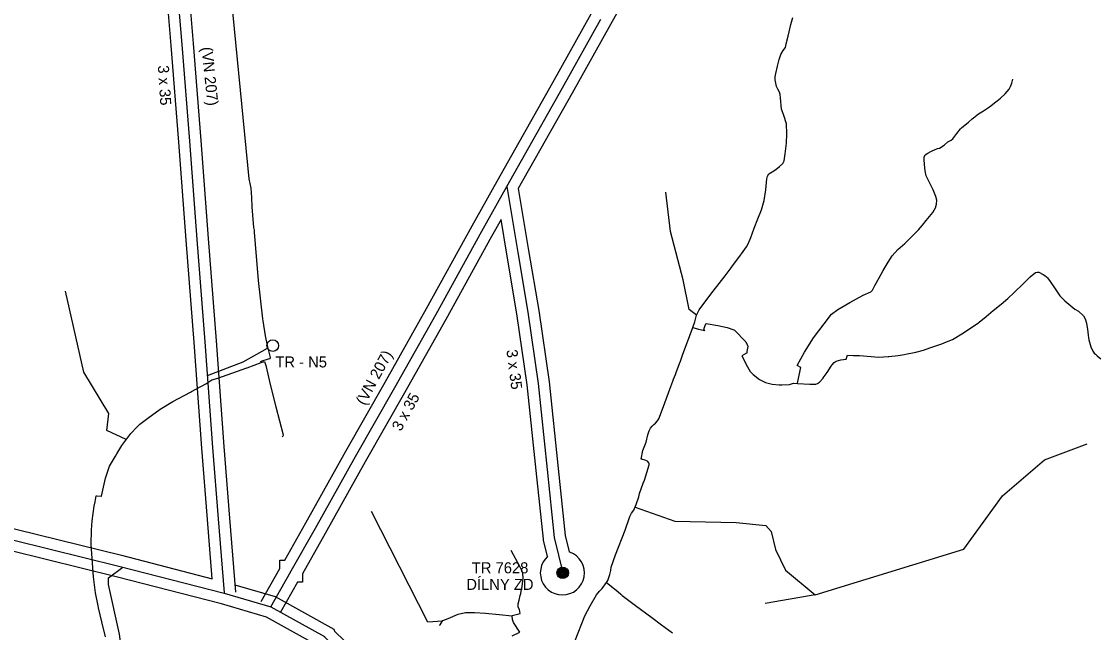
# Model space of a CAD drawing. Extents: x -439095 to -431527, y -1129525 to -1119219.
# Drawn here: x -438161 to -437185, y -1123936 to -1123382 of the extents above; entities that cross this region are included whole.
import ezdxf

# ---------------------------------------------------------------- set-up
doc = ezdxf.new("R2010")
doc.units = 0
for name, color, linetype in [('Hranice reseneho uzemi', 7, 'Continuous'), ('UZEMNI REZERVA', 7, 'Continuous'), ('Vrstva 11', 7, 'Continuous'), ('Vrstva 13', 7, 'Continuous'), ('Vrstva 19', 7, 'Continuous'), ('Vrstva 21', 7, 'Continuous'), ('ZU', 7, 'Continuous')]:
    doc.layers.add(name, color=color, linetype=linetype)

msp = doc.modelspace()

# ---------------------------------------------------------------- linework, layer by layer
at = {"layer": 'Hranice reseneho uzemi'}
for points in [[(-437977.03, -1123900.4), (-437982.65, -1123833.3), (-437982.65, -1123833.3), (-437987.74, -1123768.43), (-437994.75, -1123672.68), (-438001.8, -1123579.96), (-438008.51, -1123491), (-438015.39, -1123403.36), (-438022.11, -1123324.98), (-438003.06, -1123258.21), (-438003.06, -1123258.21), (-437981.89, -1123195.97)], [(-437935.03, -1123912.96), (-437916.84, -1123880.87), (-437916.84, -1123880.59), (-437916.74, -1123880.59), (-437916.62, -1123880.59), (-437916.52, -1123880.59), (-437916.52, -1123880.31), (-437894.53, -1123841.62), (-437858.3, -1123776.7), (-437822.65, -1123714.13), (-437785.14, -1123647.58), (-437743.7, -1123572.45), (-437721.24, -1123531.98), (-437670.6, -1123442.65), (-437636.02, -1123380.39)], [(-437721.24, -1123531.98), (-437711.29, -1123591.69), (-437702.05, -1123645.92), (-437692.72, -1123710.41), (-437684.69, -1123788.49), (-437678.09, -1123850.04), (-437678.09, -1123850.04), (-437670.47, -1123882.16), (-437670.23, -1123882.16), (-437670.23, -1123882.27)], [(-437992.51, -1123703.22), (-437960.05, -1123691.03), (-437938.12, -1123678.45)], [(-438263.63, -1123828.96), (-438072.97, -1123875.97), (-437977.31, -1123900.59), (-437935.03, -1123912.96), (-437886.52, -1123939.93), (-437886.48, -1123940.09), (-437848.4, -1123976.82), (-437836.05, -1123992.37), (-437836.05, -1123992.37), (-437821.56, -1124011.34), (-437777.52, -1124066.05), (-437725.21, -1124132.8), (-437656.19, -1124219.09), (-437594.04, -1124294.91), (-437554.42, -1124296.58), (-437554.42, -1124296.58), (-437507.95, -1124297.38), (-437407.71, -1124297.33), (-437306.88, -1124280.12), (-437197.9, -1124285.4), (-437107.85, -1124290.93)], [(-438091.73, -1124104.62), (-438075.74, -1124103.98), (-438072.64, -1124101.83), (-438063.57, -1124089.42), (-438058.56, -1124077.01), (-438058.56, -1124075.82), (-438057.61, -1124071.76), (-438062.38, -1124028.46), (-438065.61, -1123986.86), (-438072.4, -1123937.81), (-438082.18, -1123892.7), (-438082.29, -1123886.73), (-438069.22, -1123876.94)]]:
    msp.add_lwpolyline(points, dxfattribs=at)
at = {"layer": 'UZEMNI REZERVA'}
msp.add_line((-437441.55, -1123901.97), (-437486.9, -1123909.94), dxfattribs=at)
for points in [[(-437954.66, -1123524.94), (-437993.31, -1123129.35), (-437995.2, -1123092.73), (-437985.1, -1123077.57), (-437958.23, -1123072.19), (-437960.64, -1123029.38), (-437972, -1122949.82), (-437973.26, -1122876.57), (-437976.65, -1122826.24)], [(-437630.91, -1123890.86), (-437629.72, -1123889.13), (-437627.83, -1123883.75), (-437627, -1123879.92), (-437626.59, -1123877.03), (-437622.78, -1123865.69), (-437613.85, -1123843.35), (-437609.61, -1123831.09), (-437608.14, -1123828.02), (-437608.08, -1123827.95), (-437606.08, -1123825.26), (-437603.91, -1123820.19), (-437601.39, -1123813.24), (-437600.92, -1123810.22), (-437597.5, -1123800.95), (-437596.42, -1123798.04), (-437592.14, -1123784.34), (-437592.06, -1123783.31), (-437592.45, -1123782.36), (-437593.58, -1123780.89), (-437596.73, -1123779.74), (-437598.08, -1123779.31), (-437598.78, -1123779.12), (-437599.42, -1123779.04), (-437597.78, -1123771.31), (-437594.8, -1123763.72), (-437593.39, -1123757.08), (-437592.02, -1123753.46), (-437590.78, -1123751.15), (-437589.28, -1123749.23), (-437587.81, -1123747.66), (-437586.52, -1123746.41), (-437584.63, -1123744.53), (-437583.22, -1123742.57), (-437579.11, -1123731.36), (-437573.38, -1123715.77), (-437570.7, -1123708.53), (-437569.95, -1123706.64), (-437568.3, -1123702.4), (-437567.61, -1123700.49), (-437564.59, -1123692.34), (-437563.62, -1123690.3), (-437561.76, -1123685.02), (-437552.43, -1123659.91), (-437550.85, -1123654.8), (-437550.5, -1123653.53), (-437549.18, -1123648.66), (-437548.29, -1123646.66), (-437546.75, -1123643.82), (-437541.58, -1123636.84), (-437534.02, -1123626.92), (-437523.3, -1123612.86), (-437517.76, -1123605.67), (-437516.42, -1123604), (-437510.84, -1123596.25), (-437506.82, -1123590.98), (-437503.9, -1123586.77), (-437502.81, -1123584.72), (-437500.57, -1123579.88), (-437500, -1123578.21), (-437496.98, -1123569.71), (-437493.56, -1123561.22), (-437490.29, -1123553.08), (-437487.95, -1123544.59), (-437486.44, -1123535.17), (-437485.52, -1123525.15), (-437484.97, -1123522.61), (-437483.6, -1123520.56), (-437480.46, -1123518.65), (-437477.24, -1123516.69), (-437473.89, -1123513.96), (-437470.91, -1123511.12), (-437469.67, -1123508.79), (-437468.73, -1123502.4), (-437468.46, -1123500), (-437467.68, -1123492.77), (-437467.38, -1123484.39), (-437467.76, -1123475.1), (-437469.97, -1123467.67), (-437471.5, -1123463.41), (-437472.08, -1123462.05), (-437473.15, -1123451.6), (-437473.38, -1123448.7), (-437474.11, -1123446.63), (-437475.48, -1123443.89), (-437476.64, -1123441.29), (-437477.76, -1123435.45), (-437477.75, -1123432.72), (-437477.27, -1123429.45), (-437475.84, -1123422.85), (-437474.17, -1123416.89), (-437472.76, -1123412.51), (-437470.53, -1123408.69), (-437468.67, -1123406.15), (-437467.81, -1123402.84), (-437466.23, -1123395.88), (-437463.54, -1123385.15), (-437461.91, -1123378.82)], [(-437552.43, -1123659.91), (-437547.4, -1123661.38), (-437543.04, -1123662.1), (-437542.46, -1123662.31), (-437542.05, -1123662.49), (-437541.78, -1123662.3), (-437542.46, -1123662.31), (-437542.19, -1123660.39), (-437540.7, -1123656.44), (-437540.38, -1123656.03), (-437529.82, -1123657.91), (-437521.47, -1123659.92), (-437515.27, -1123662), (-437514.79, -1123662.28), (-437504.44, -1123672.87), (-437502.92, -1123676.06), (-437502.71, -1123676.7), (-437502.6, -1123677.02), (-437503.45, -1123681.7), (-437503.66, -1123682.92), (-437503.67, -1123682.95), (-437503.79, -1123683.11), (-437508.15, -1123685.61), (-437502.93, -1123695.58), (-437500.55, -1123699.59), (-437500, -1123700.16), (-437497.81, -1123702.42), (-437492.2, -1123706.88), (-437486.65, -1123709.54), (-437480.7, -1123711.04), (-437474.29, -1123711.65), (-437471.73, -1123711.89), (-437464.76, -1123711.36), (-437461.27, -1123710.28), (-437457.61, -1123710.42), (-437457.6, -1123710.17), (-437455.2, -1123698.69), (-437454.48, -1123696.15), (-437457.87, -1123694.15), (-437451.36, -1123682.19), (-437443.13, -1123669.12), (-437433.55, -1123656.54), (-437426.75, -1123647.74), (-437421.21, -1123643.39), (-437410.19, -1123637.29), (-437397.97, -1123630.37), (-437391.25, -1123627.45), (-437389.68, -1123625.86), (-437387.4, -1123621.82), (-437383.47, -1123614.86), (-437380.05, -1123608.09), (-437375.43, -1123600.45), (-437371.74, -1123594.7), (-437366.71, -1123589.2), (-437360.47, -1123583.64), (-437352.36, -1123575.87), (-437348.09, -1123571.14), (-437344.37, -1123566.92), (-437340.91, -1123562.79), (-437335.08, -1123555.49), (-437332.6, -1123551.41), (-437331.57, -1123547.95), (-437331.48, -1123544.45), (-437332.22, -1123541.13), (-437334.8, -1123534.98), (-437338.38, -1123527.87), (-437338.68, -1123527.19), (-437340.91, -1123522.22), (-437341.86, -1123517.76), (-437342.44, -1123511.94), (-437342.96, -1123507.39), (-437342.67, -1123505.3), (-437341.79, -1123503.38), (-437339.45, -1123501.78), (-437336.72, -1123500.22), (-437336.2, -1123500), (-437335.64, -1123499.75), (-437333.45, -1123498.9), (-437330.67, -1123497.59), (-437328.9, -1123497.16), (-437324.76, -1123494.67), (-437321.24, -1123491.65), (-437319.55, -1123490.72), (-437318.19, -1123490.14), (-437316.68, -1123488.69), (-437313.24, -1123483.89), (-437309.87, -1123479.83), (-437308.83, -1123478.82), (-437302.64, -1123473.56), (-437299.19, -1123470.62), (-437298.13, -1123469.69), (-437293.61, -1123466.1), (-437289.06, -1123463.31), (-437283.61, -1123459.73), (-437277.85, -1123455.39), (-437276.65, -1123454.39), (-437273.47, -1123451.85), (-437269.39, -1123448.02), (-437265.9, -1123443.84), (-437264.4, -1123441.43), (-437263.29, -1123438.44), (-437262.3, -1123434.62)], [(-437943.89, -1123691.64), (-437944.11, -1123690.55), (-437942.82, -1123690.13), (-437937.12, -1123688.26), (-437935.64, -1123687.79), (-437935.33, -1123686.86), (-437938.07, -1123676.03), (-437939.85, -1123667.26), (-437942.08, -1123653.74), (-437942.41, -1123651.97), (-437946.16, -1123617.24), (-437947.73, -1123598.79), (-437950.03, -1123573.71), (-437949.81, -1123572.25), (-437949.86, -1123571.92), (-437949.91, -1123571.6), (-437950.46, -1123569.07), (-437951.98, -1123550.34), (-437952.3, -1123542.04), (-437953.01, -1123533.62), (-437954.66, -1123524.94)], [(-437549.18, -1123648.66), (-437555.98, -1123643.46), (-437561.33, -1123616.53), (-437572.9, -1123572.82), (-437576.87, -1123537.13)], [(-437457.61, -1123710.42), (-437446.48, -1123711.22), (-437441, -1123711.05), (-437439.51, -1123710.62), (-437437.55, -1123709.29), (-437434.45, -1123705.7), (-437434.23, -1123705.45), (-437430.61, -1123700.49), (-437427.15, -1123694.78), (-437426.13, -1123693.52), (-437424.34, -1123691.64), (-437422.68, -1123690.3), (-437418.46, -1123688.96), (-437413.6, -1123688.38), (-437412.34, -1123685), (-437407.22, -1123685.16), (-437401.32, -1123685.25), (-437384.01, -1123686.58), (-437375.45, -1123686.18), (-437374.76, -1123686.1), (-437366.51, -1123685.2), (-437360.93, -1123684.22), (-437358.18, -1123683.74), (-437353.26, -1123682.73), (-437350.48, -1123682.16), (-437343.3, -1123680.23), (-437337.77, -1123678.35), (-437326.94, -1123674.64), (-437322.47, -1123672.92), (-437317.08, -1123670.54), (-437307.11, -1123664.52), (-437299.63, -1123659.62), (-437293.7, -1123655.43), (-437293, -1123654.93), (-437286.74, -1123649.85), (-437280.19, -1123644.54), (-437272.91, -1123638.76), (-437266.86, -1123633.57), (-437261.27, -1123628.1), (-437253.2, -1123620.11), (-437246.81, -1123613.79), (-437242.01, -1123609.98), (-437240.31, -1123609.59), (-437238.88, -1123609.79), (-437234.97, -1123611.84), (-437233.31, -1123612.6), (-437231.86, -1123613.88), (-437231.06, -1123614.82), (-437228.63, -1123618.08), (-437224.18, -1123624.89), (-437219.93, -1123631.16), (-437215.26, -1123635.54), (-437206.15, -1123643.27), (-437203, -1123645.09), (-437198.25, -1123649.25), (-437196.8, -1123651.97), (-437195.62, -1123656.01), (-437194.63, -1123661.65), (-437194.42, -1123663.68), (-437194.08, -1123666.96), (-437193.86, -1123668.98), (-437193.55, -1123670.97), (-437191.66, -1123677.26), (-437189.8, -1123681.29), (-437188.59, -1123682.92), (-437187.59, -1123683.88), (-437186.03, -1123685.39), (-437182.66, -1123688.06)], [(-438066.16, -1123761.3), (-438083.8, -1123753.28), (-438081.95, -1123737.87), (-438104.74, -1123700.26), (-438121.38, -1123626.9)], [(-438085.03, -1123940.1), (-438088.36, -1123926.52), (-438091.39, -1123913.78), (-438091.76, -1123912.2), (-438094.01, -1123900.14), (-438095.87, -1123885.89), (-438097.02, -1123869.18), (-438097.93, -1123856.05), (-438097.79, -1123843.46), (-438096.98, -1123835.14), (-438095.15, -1123821.75), (-438094.39, -1123817.93), (-438093.29, -1123812.23), (-438092.97, -1123812.27), (-438088.91, -1123812.73), (-438088.59, -1123812.77), (-438085.01, -1123796.25), (-438081.24, -1123785.49), (-438076.05, -1123776.48), (-438074.58, -1123774.36), (-438070.25, -1123766.86), (-438062.08, -1123755.75), (-438056.24, -1123749.75), (-438053.93, -1123747.37), (-438046.57, -1123741.89), (-438035.52, -1123733.96), (-438023.79, -1123726.89), (-438007.87, -1123718.3), (-438007.08, -1123717.87), (-437994, -1123710.79), (-437991.33, -1123709), (-437988.51, -1123707.26), (-437983.26, -1123705.73), (-437956.96, -1123696.35), (-437956.58, -1123696.21), (-437943.89, -1123691.64), (-437940.93, -1123690.55), (-437939.73, -1123694.29), (-437935.31, -1123712.76), (-437930.44, -1123731.59), (-437924.01, -1123757.12), (-437924.22, -1123758.18), (-437924.77, -1123759.04)], [(-437604.8, -1123822.66), (-437568.84, -1123835.34), (-437541.12, -1123835.96), (-437513.39, -1123836.57), (-437486.3, -1123839.33), (-437481.41, -1123844.7), (-437477.63, -1123861.12), (-437473.13, -1123870.43), (-437468.63, -1123879.75), (-437441.55, -1123901.97), (-437306.99, -1123860.62), (-437271.84, -1123812.5), (-437233.63, -1123779.69), (-437195.12, -1123765.17)], [(-437779.4, -1123925.84), (-437792.86, -1123926.76), (-437843.71, -1123826.43)], [(-437716.26, -1123939.33), (-437709.42, -1123935.82), (-437714.98, -1123927.06), (-437715.87, -1123924.5), (-437716.19, -1123921), (-437716.21, -1123920.7), (-437709.07, -1123919.09), (-437709.67, -1123915.34), (-437710.79, -1123913.28), (-437710.81, -1123910.12), (-437710.1, -1123906.92), (-437709.13, -1123902.77), (-437708.55, -1123900.79), (-437708.2, -1123898.89), (-437707.24, -1123894.47), (-437706.25, -1123887.04), (-437706.64, -1123882.54), (-437707.85, -1123879.36), (-437709.15, -1123876.91), (-437717.27, -1123861.95)], [(-437659.16, -1123943.4), (-437650.52, -1123921.14), (-437645.71, -1123911.92), (-437639.95, -1123902.15), (-437637.06, -1123898.91), (-437634.73, -1123896.3), (-437630.91, -1123890.86)], [(-437630.91, -1123890.86), (-437620.52, -1123899.06), (-437620.14, -1123899.42), (-437620.14, -1123899.42), (-437617.93, -1123901.53), (-437617.3, -1123902.06), (-437616.67, -1123902.59), (-437604.41, -1123911.66), (-437589.65, -1123922.61), (-437580.82, -1123929.39), (-437570.87, -1123936.44)], [(-437782.18, -1123929.73), (-437781.64, -1123929.23), (-437779.74, -1123926.29), (-437779.06, -1123925.4), (-437774.35, -1123923.49), (-437765.26, -1123919.56), (-437758.73, -1123918.11), (-437750.37, -1123918.21), (-437740.5, -1123918.74), (-437728.24, -1123919.78), (-437716.19, -1123921)]]:
    msp.add_lwpolyline(points, dxfattribs=at)
at = {"layer": 'Vrstva 11'}
for radius in [5.25, 4.55, 3.85, 3.15, 2.45, 1.75, 1.05, 0.35]:
    msp.add_circle((-437670.47, -1123882.16), radius, dxfattribs=at)
at = {"layer": 'Vrstva 19'}
msp.add_circle((-437933.35, -1123676.26), 5.25, dxfattribs=at)
at = {"layer": 'ZU'}
for points in [[(-437943.73, -1123908.03), (-437926.83, -1123878.23), (-437926.83, -1123870.61), (-437922.51, -1123870.6), (-437903.24, -1123836.71), (-437867.01, -1123771.79), (-437831.35, -1123709.2), (-437793.87, -1123642.71), (-437752.45, -1123567.61), (-437729.96, -1123527.09), (-437679.32, -1123437.76), (-437644.76, -1123375.53), (-437606.33, -1123306.58), (-437572.73, -1123246.44), (-437546.8, -1123200.89), (-437515.68, -1123145.34), (-437486.01, -1123090.7), (-437452.03, -1123030.97), (-437414.19, -1122963.66), (-437373.12, -1122887.85), (-437344.42, -1122836.36), (-437323.98, -1122774.46), (-437315.27, -1122728.16)], [(-437504.06, -1123165.53), (-437529.38, -1123210.73), (-437555.31, -1123256.26), (-437588.87, -1123316.32), (-437627.28, -1123385.25), (-437661.88, -1123447.54), (-437710.79, -1123533.83)], [(-437988.14, -1123887.48), (-437992.65, -1123833.72), (-437992.65, -1123833.69), (-437997.71, -1123769.19), (-438004.72, -1123673.42), (-438011.77, -1123580.72), (-438018.48, -1123491.77), (-438025.36, -1123404.18), (-438032.23, -1123324), (-438012.62, -1123255.26), (-438012.54, -1123255.02), (-438000.32, -1123219.09)], [(-437981.38, -1123225.52), (-437993.51, -1123261.2), (-438011.99, -1123325.96), (-438005.42, -1123402.54), (-437998.54, -1123490.23), (-437991.83, -1123579.2), (-437984.78, -1123671.94), (-437977.77, -1123767.67), (-437972.68, -1123832.58), (-437967.06, -1123899.57)], [(-437710.79, -1123533.83), (-437701.43, -1123590.03), (-437692.17, -1123644.37), (-437682.8, -1123709.18), (-437674.74, -1123787.45), (-437668.21, -1123848.34), (-437664.69, -1123863.22)], [(-437726.4, -1123561.88), (-437734.95, -1123577.29), (-437776.41, -1123652.45), (-437813.95, -1123719.06), (-437849.59, -1123781.61), (-437885.82, -1123846.53), (-437906.52, -1123882.95), (-437906.52, -1123890.61), (-437910.86, -1123890.6), (-437926.33, -1123917.89)], [(-437684.23, -1123867.49), (-437687.8, -1123852.41), (-437687.96, -1123851.79), (-437694.64, -1123789.53), (-437702.65, -1123711.64), (-437711.93, -1123647.48), (-437721.15, -1123593.35), (-437726.4, -1123561.88)], [(-439086.08, -1123604.53), (-439004.4, -1123631.04), (-438833.27, -1123675.98), (-438365.06, -1123791.27), (-438261.13, -1123819.28), (-438070.53, -1123866.27), (-437988.14, -1123887.48)], [(-437892.75, -1123947.93), (-437892.82, -1123947.87), (-437938.91, -1123922.24), (-437979.96, -1123910.23), (-438075.42, -1123885.67), (-438266.12, -1123838.65), (-438370.06, -1123810.64), (-438396.17, -1123804.21)], [(-437684.23, -1123867.49), (-437686.1, -1123869.36), (-437688.1, -1123872.21), (-437689.57, -1123875.37), (-437690.47, -1123878.74), (-437690.78, -1123882.21), (-437690.47, -1123885.69), (-437689.57, -1123889.05), (-437688.1, -1123892.21), (-437686.1, -1123895.07), (-437683.63, -1123897.53), (-437680.78, -1123899.53), (-437677.62, -1123901.01), (-437674.25, -1123901.91), (-437670.78, -1123902.21), (-437667.3, -1123901.91), (-437663.94, -1123901.01), (-437660.78, -1123899.53), (-437657.92, -1123897.53), (-437655.45, -1123895.07), (-437653.46, -1123892.21), (-437651.98, -1123889.05), (-437651.08, -1123885.69), (-437650.78, -1123882.21), (-437651.08, -1123878.74), (-437651.98, -1123875.37), (-437653.46, -1123872.21), (-437655.45, -1123869.36), (-437657.92, -1123866.89), (-437660.78, -1123864.89), (-437663.94, -1123863.42), (-437664.69, -1123863.22)], [(-437967.61, -1123893.01), (-437931.15, -1123903.68), (-437877.87, -1123933.3), (-437877.47, -1123934.88), (-437840.98, -1123970.08), (-437829.99, -1123983.93)]]:
    msp.add_lwpolyline(points, dxfattribs=at)

# ---------------------------------------------------------------- texts
at = {"layer": 'Vrstva 13'}
for s, rotation, p in [('(VN 207)', 275.95224, (-437998.01, -1123406.02)), ('3 x 35', 273.59133, (-438037.53, -1123422.42)), ('(VN 207)', 61.69913, (-437849.83, -1123731.04)), ('3 x 35', 277.27564, (-437721.58, -1123680.38)), ('3 x 35', 61.24725, (-437817.26, -1123754.55))]:
    msp.add_text(s, height=10, rotation=rotation, dxfattribs=at).set_placement(p)
for s, p in [('TR 7628', (-437752.91, -1123882.6)), ('DÍLNY ZD', (-437757.88, -1123897.6))]:
    msp.add_text(s, height=10, dxfattribs=at).set_placement(p)
at = {"layer": 'Vrstva 21'}
msp.add_text('TR - N5', height=10, dxfattribs=at).set_placement((-437930.99, -1123695.99))

doc.saveas('drawing.dxf')
